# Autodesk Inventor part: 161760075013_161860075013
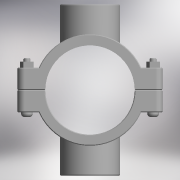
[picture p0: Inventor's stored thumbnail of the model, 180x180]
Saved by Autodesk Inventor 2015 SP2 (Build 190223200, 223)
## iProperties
Created: 2017-05
Part Number: 161760075013_161860075013
Material: Generic
Description: PLASSON DOUBLE SADDLE 75-1.1/4"
Document SubType Name: Modeling
Designer: KIM
Density: 1 g/cm^3
Appearance: Default
Author: KIM
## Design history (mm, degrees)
derived "16176.ipt"
feature "Solid1::16176.ipt"
feature "Solid2::16176.ipt"
tag "TaggingFeature1"
body "Solid1"
body "Solid2"
other parameters: "d0" = 93.75, "d1" = 122, "d2" = 37.5, "d3" = 75, "d4" = 98, "d5" = 0, "d6" = 6.1, "d7" = 122, "d8" = 0.1, "d10" = 0, "d11" = 0.75, "d20" = 0.75, "d23" = 0.75, "d37" = 8, "d38" = 45.5, "d39" = 0, "d40" = 3, "d41" = 5, "d42" = 0, "d43" = 6, "d44" = 3, "d45" = 0, "d46" = 0.75, "d52" = 38.952, "d53" = 25, "d54" = 0, "d55" = 32, "d57" = 0, "d58" = 81, "d60" = 0, "d63" = 8, "d66" = 82, "d67" = 144, "d68" = 50.6376, "d69" = 38.952, "d70" = 25, "d71" = 0, "d72" = 32, "d74" = 0, "d75" = 0.75, "d_" = 75, "B_" = 32, "G_" = 38.952, "A_" = 72, "L_" = 122, "L_1" = 98, "l_2" = 25
